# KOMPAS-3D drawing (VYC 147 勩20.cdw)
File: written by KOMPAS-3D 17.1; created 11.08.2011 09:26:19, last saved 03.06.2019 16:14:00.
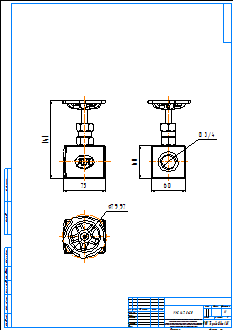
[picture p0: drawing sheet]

Sheet 1: A2, portrait

Title block, sheet 1: name: VYC 147 Ду20; material: Внимание! Данный продукт является объектом авторского права ООО «Торговый Дом АДЛ». / Запрещается изменение, копирование, распространение / (в том числе путем копирования на другие сайты и ресурсы в Интернете) / или любое иное использование информации и объектов без предварительного / согласия правообладателя (ООО «Торговый Дом АДЛ»).; scale: 1:1; sheets: 1; organisation: ООО "Торговый дом АДЛ"; sheet format: A2; stored path: \\adlc.lan\data\АДЛ_ПКД\3D-модели\Поставщики\VYC Industrial\VYC 147\KOMPAS 2D\VYC 147 Ду20.cdw

Views: Спереди 1, Проекционный вид 2, Проекционный вид 3
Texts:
  bsv
  adl
Dimensions and other numbers on the sheet: 75; 141; 60; 79,97; 1:1; 1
